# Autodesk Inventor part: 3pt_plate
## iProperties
Shininess: 64.0
Length Units: 11269
Angle Units: 11279
Time Units: 11290
Mass Units: 11283
Length Display Precision: 3
Angle Display Precision: 2
Compacted: True
Part Number: 3pt_plate
Document SubType Name: Modeling
Created: 2004-08
Designer: John Blackburn
Manufacturer: Standard
Standards Organization: Custom
Material: Aluminum-6061
Density: 0.0
Volumn: 0.0
Area: 0.0
PropertySet Name: Model Information
Control State: 0
Master: False
Checked Out: False
Author: John Blackburn
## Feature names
1. Extrusion1
2. Hole1
